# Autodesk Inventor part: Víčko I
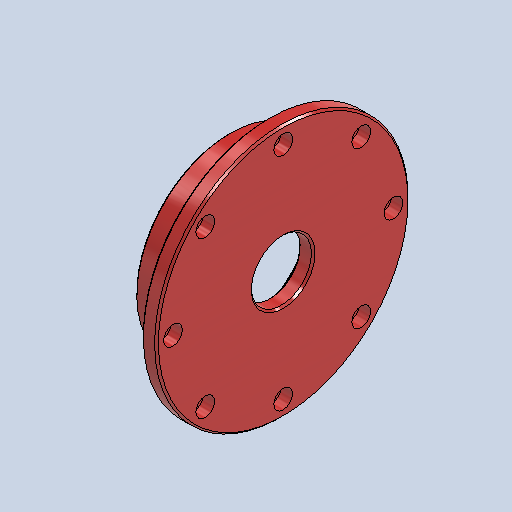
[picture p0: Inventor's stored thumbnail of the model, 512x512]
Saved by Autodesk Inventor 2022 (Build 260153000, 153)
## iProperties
Created: 2025-05
Part Number: Víčko I
Material: Všeobecné
Document SubType Name: Modeling
Designer: jbart
Density: 1 g/cm^3
Appearance: Oranžovo-červená
Mass: 1078.22 g
Surface Area: 1745.39 cm^2
Volume: 1078.22 cm^3
Author: jbart
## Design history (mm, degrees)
sketch "Náčrt1"
  geometry: L1 (0, 0)-(52, 0); L2 (52, 32)-(52, 135); L3 (52, 135)-(36, 135); L4 (36, 135)-(36, 100); L5 (36, 100)-(-6, 100); L6 (-6, 100)-(-6, 90); L7 (-6, 90)-(36, 90); L8 (36, 90)-(36, 32); L9 (36, 32)-(52, 32); 3 further points
  constraints: 18 end point, 6 perpendicular, 3 midpoint, 2 horizontal, 2 vertical alignment, 1 vertical
  dimensions: "d0" = 52 distance of L1.start L1.end; "d5" = 16 distance of L2.end L3.end; "d6" = 270 diameter of L3 L1; "d7" = 180 diameter of L7 L1; "d8" = 64 diameter of L9 L1; "d9" = 42 distance of L6.end L7.end; "d10" = 200 diameter of L5 L1
revolve "Rotace1" sketch "Náčrt1" stored, may be unused: angle "d11" = 90 deg
chamfer "Zkosení1" distance "d12" = 2; stored, may be unused: second distance "d13" = 2, angle "d14" = 45 deg
fillet "Zaoblení1" dims "d15" = 5
sketch "Náčrt2" dims "d16" = 235
  geometry: L1 (0, 0)-(0, 117.5); C1 r 32 at (0, 0) reference; 3 further points
  constraints: 2 coincident, 2 end point, 1 vertical, 1 vertical alignment, 2 other
hole "Díra1" sketch "Náčrt2" at (0, 117.5) diameter "d17" = 13; stored, may be unused: countersink angle "d21" = 90 deg, drill point angle "d23" = 118 deg; dims "d18" = 15, "d19" = 20, "d20" = 12, "d22" = 20
pattern_circular "Kruhové pole1" dims angle "d25" = 360 deg
fillet "Zaoblení2" dims "d27" = 2
chamfer "Zkosení2" distance "d28" = 2; stored, may be unused: second distance "d29" = 2, angle "d30" = 45 deg
node "Těleso1"
